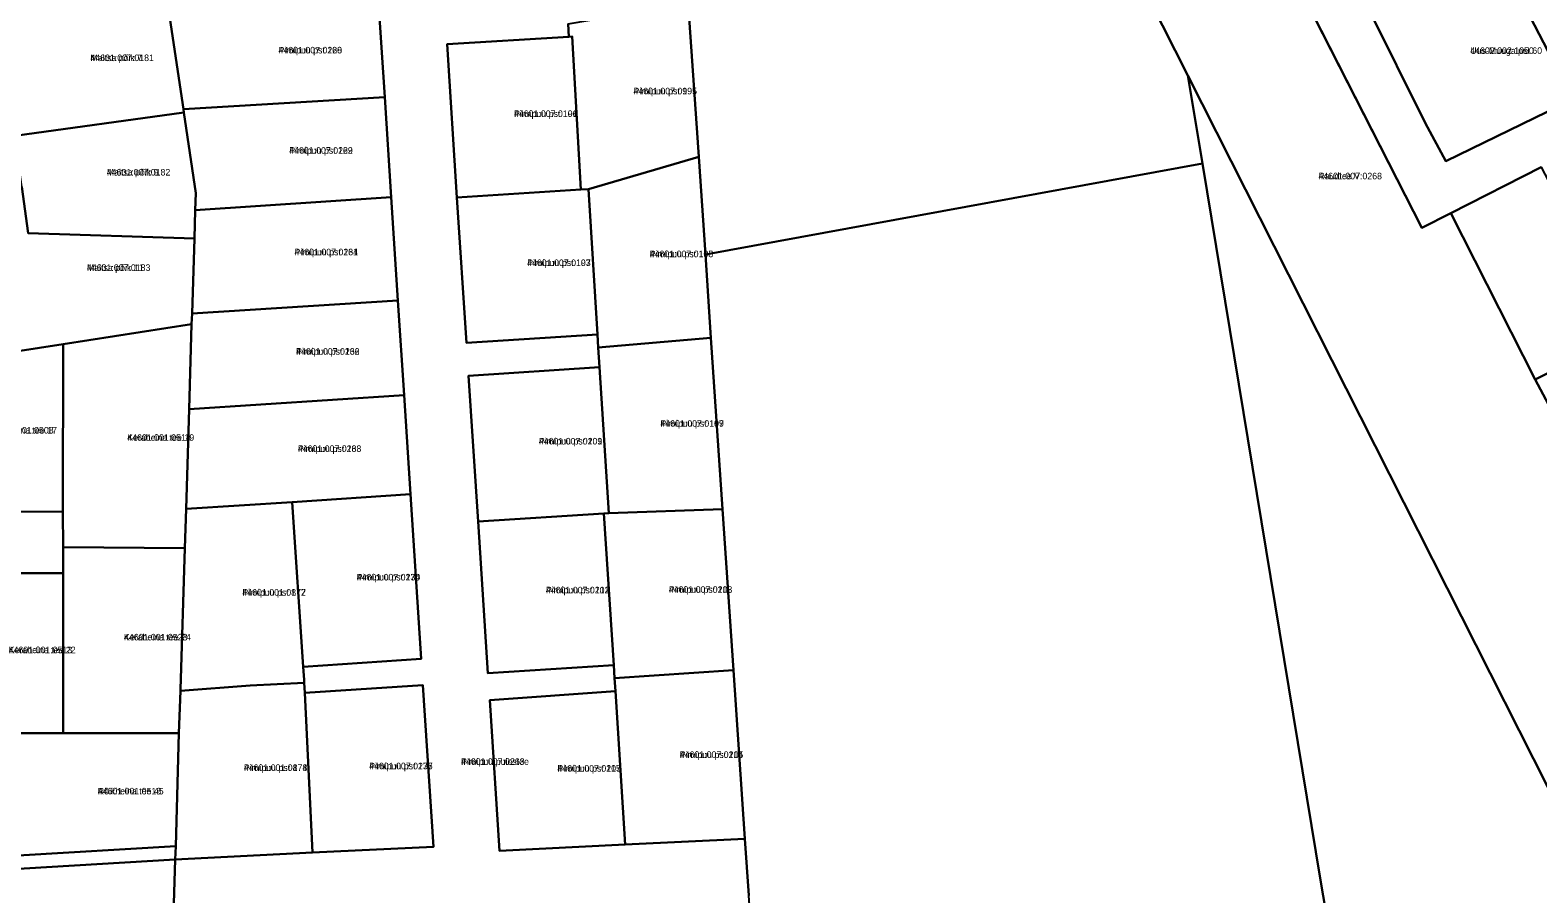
# Model space of a CAD drawing. Extents: x 551843 to 558501, y 6589003 to 6595718.
# Drawn here: x 554378.5 to 554722.9, y 6592716.7 to 6592914.1 of the extents above; entities that cross this region are included whole.
import ezdxf

# ---------------------------------------------------------------- set-up
doc = ezdxf.new("R2010")
doc.units = 0
for name, color, linetype in [('L_AADRESS', 7, 'Continuous'), ('PIIR', 7, 'Continuous'), ('TUNNUS', 7, 'Continuous')]:
    doc.layers.add(name, color=color, linetype=linetype)

msp = doc.modelspace()

# ---------------------------------------------------------------- linework, layer by layer
at = {"layer": 'PIIR'}
for points in [[(554923.69, 6592347.53), (554878.41, 6592438.09), (554841.8, 6592510.41), (554771.18, 6592649.95), (554642.95, 6592903.73), (554573.43, 6593041.09), (554529.22, 6593128.57), (554464.48, 6593256.08), (554446.62, 6593289.09), (554441.09, 6593299.31), (554261.19, 6593527.78)], [(554487.14, 6593279.28), (554574.16, 6593108.63), (554585.26, 6593086.87), (554696.4, 6592868.94), (554702.95, 6592872.25), (554722.28, 6592834.27), (554727.72, 6592823.94)], [(554723.65, 6592882.76), (554702.95, 6592872.25), (554696.4, 6592868.94), (554643.69, 6592972.29), (554655.06, 6592977.69), (554671.09, 6592945.33), (554684.09, 6592919.15), (554697.11, 6592892.89), (554701.82, 6592884.15), (554730.76, 6592898.25)], [(554726.23, 6592907.32), (554712.86, 6592933.09)], [(554411.2, 6592709.5), (554411.66, 6592724.59), (554442.98, 6592726.12), (554470.64, 6592727.48), (554468.24, 6592764.38), (554441.26, 6592762.61), (554441.12, 6592764.9), (554441.11, 6592765.62), (554440.9, 6592768.62), (554467.85, 6592770.38), (554465.4, 6592808.08), (554463.93, 6592830.7), (554462.52, 6592852.34), (554460.98, 6592875.93), (554459.5, 6592898.77), (554458.02, 6592921.54)], [(554501.42, 6592915.58), (554501.57, 6592912.59), (554473.73, 6592910.9), (554476.01, 6592875.84), (554478.17, 6592842.6), (554508.07, 6592844.54), (554508.25, 6592841.54), (554508.55, 6592837.06), (554478.66, 6592835.1), (554480.83, 6592801.77), (554483.08, 6592767.12), (554511.82, 6592768.99), (554512.01, 6592766), (554512.2, 6592763), (554483.48, 6592760.97), (554485.72, 6592726.56), (554514.4, 6592727.96), (554541.78, 6592729.29), (554542.67, 6592716.34)], [(554727.72, 6592823.94), (554722.28, 6592834.27), (554743.42, 6592844.96)]]:
    msp.add_lwpolyline(points, dxfattribs=at)
for points in [[(554521.16, 6593033.4), (554540.12, 6593036.49), (554560.01, 6593039.24), (554573.43, 6593041.09), (554642.95, 6592903.73), (554646.24, 6592883.65), (554532.75, 6592862.8), (554531.22, 6592885.11), (554528.84, 6592920.17), (554526.55, 6592953.9), (554523.81, 6592994.34)], [(554697.11, 6592892.89), (554684.09, 6592919.15), (554712.86, 6592933.09), (554726.23, 6592907.32), (554730.76, 6592898.25), (554701.82, 6592884.15)], [(554371.05, 6592918.84), (554409.37, 6592924.1), (554410.22, 6592918.36), (554413.54, 6592896.01), (554413.66, 6592895.25), (554375.02, 6592889.95)], [(554410.22, 6592918.36), (554458.02, 6592921.54), (554459.5, 6592898.77), (554413.54, 6592896.01)], [(554501.42, 6592915.58), (554528.84, 6592920.17), (554531.22, 6592885.11), (554506.03, 6592877.79), (554504.33, 6592877.68), (554502.32, 6592912.63), (554501.57, 6592912.59)], [(554473.73, 6592910.9), (554501.57, 6592912.59), (554502.32, 6592912.63), (554504.33, 6592877.68), (554476.01, 6592875.84)], [(554745.26, 6592499.11), (554711.7, 6592493.45), (554704.16, 6592538.17), (554673.19, 6592719.82), (554646.24, 6592883.65), (554642.93, 6592903.77), (554771.18, 6592649.95), (554841.8, 6592510.41), (554768.62, 6592501.84)], [(554413.54, 6592896.01), (554459.5, 6592898.77), (554460.98, 6592875.93), (554416.25, 6592872.95), (554416.39, 6592876.86), (554413.66, 6592895.25)], [(554375.02, 6592889.95), (554413.66, 6592895.25), (554416.39, 6592876.86), (554416.25, 6592872.95), (554416.07, 6592866.52), (554378.07, 6592867.69), (554376.62, 6592878.3)], [(554506.03, 6592877.79), (554531.22, 6592885.11), (554532.75, 6592862.8), (554534.02, 6592843.8), (554508.25, 6592841.54), (554508.07, 6592844.54)], [(554534.02, 6592843.8), (554532.75, 6592862.8), (554646.24, 6592883.65), (554673.19, 6592719.82), (554704.16, 6592538.17), (554568.26, 6592508.78), (554555.84, 6592506.03), (554554.24, 6592531.14), (554551.93, 6592568.73), (554549.6, 6592606.49), (554547.29, 6592643.76), (554544.98, 6592681.09), (554544.18, 6592694.26), (554542.67, 6592716.34), (554541.78, 6592729.29), (554539.18, 6592767.79), (554536.68, 6592804.63)], [(554722.28, 6592834.27), (554702.95, 6592872.25), (554723.65, 6592882.76), (554743.42, 6592844.96)], [(554364.77, 6592876.42), (554376.62, 6592878.3), (554378.07, 6592867.69), (554416.07, 6592866.52), (554415.52, 6592849.35), (554415.39, 6592846.94), (554386.06, 6592842.35), (554369.77, 6592839.83)], [(554416.25, 6592872.95), (554460.98, 6592875.93), (554462.52, 6592852.34), (554415.52, 6592849.35), (554416.07, 6592866.52)], [(554476.01, 6592875.84), (554504.33, 6592877.68), (554506.03, 6592877.79), (554508.07, 6592844.54), (554478.17, 6592842.6)], [(554415.52, 6592849.35), (554462.52, 6592852.34), (554463.93, 6592830.7), (554414.85, 6592827.5), (554415.39, 6592846.94)], [(554386.02, 6592804.03), (554386.06, 6592842.35), (554415.39, 6592846.94), (554414.85, 6592827.5), (554414.16, 6592804.69), (554413.87, 6592795.74), (554386.04, 6592795.97)], [(554352.81, 6592804.06), (554352.72, 6592837.18), (554369.77, 6592839.83), (554386.06, 6592842.35), (554386.02, 6592804.03)], [(554508.25, 6592841.54), (554534.02, 6592843.8), (554536.68, 6592804.63), (554510.72, 6592803.72), (554508.55, 6592837.06)], [(554478.66, 6592835.1), (554508.55, 6592837.06), (554510.72, 6592803.72), (554509.57, 6592803.64), (554480.83, 6592801.77)], [(554414.85, 6592827.5), (554463.93, 6592830.7), (554465.4, 6592808.08), (554438.37, 6592806.23), (554414.16, 6592804.69)], [(554269.06, 6592818.81), (554268.83, 6592823.82), (554279.26, 6592825.48), (554282.7, 6592802), (554318.6, 6592802.02), (554352.8, 6592801.98), (554352.81, 6592804.06), (554386.02, 6592804.03), (554386.04, 6592795.97), (554386.03, 6592790), (554361.23, 6592789.98), (554336.17, 6592790.01), (554310.03, 6592790.01), (554281.23, 6592789.98), (554271.27, 6592790.01), (554270.06, 6592806.81)], [(554438.37, 6592806.23), (554465.4, 6592808.08), (554467.85, 6592770.38), (554440.9, 6592768.62)], [(554413.87, 6592795.74), (554414.16, 6592804.69), (554438.37, 6592806.23), (554440.9, 6592768.62), (554441.11, 6592765.62), (554441.12, 6592764.9), (554428.77, 6592764.33), (554412.89, 6592763.14), (554412.86, 6592763.39)], [(554480.83, 6592801.77), (554509.57, 6592803.64), (554511.82, 6592768.99), (554483.08, 6592767.12)], [(554509.57, 6592803.64), (554510.72, 6592803.72), (554536.68, 6592804.63), (554539.18, 6592767.79), (554512.01, 6592766), (554511.82, 6592768.99)], [(554386.03, 6592790), (554386.04, 6592795.97), (554413.87, 6592795.74), (554412.86, 6592763.39), (554412.89, 6592763.14), (554412.52, 6592753.39), (554386.04, 6592753.39)], [(554361.26, 6592753.4), (554361.23, 6592789.98), (554386.03, 6592790), (554386.04, 6592753.39), (554375.81, 6592753.4)], [(554512.01, 6592766), (554539.18, 6592767.79), (554541.78, 6592729.29), (554514.4, 6592727.96), (554512.2, 6592763)], [(554412.52, 6592753.39), (554412.89, 6592763.14), (554428.77, 6592764.33), (554441.12, 6592764.9), (554441.26, 6592762.61), (554442.98, 6592726.12), (554411.66, 6592724.59), (554411.77, 6592727.61)], [(554441.26, 6592762.61), (554468.24, 6592764.38), (554470.64, 6592727.48), (554442.98, 6592726.12)], [(554483.48, 6592760.97), (554512.2, 6592763), (554514.4, 6592727.96), (554485.72, 6592726.56)], [(554375.79, 6592725.47), (554375.81, 6592753.4), (554386.04, 6592753.39), (554412.52, 6592753.39), (554411.77, 6592727.61)], [(554286.44, 6592717.06), (554286.23, 6592720.04), (554313.92, 6592721.75), (554343.7, 6592723.47), (554375.79, 6592725.47), (554411.77, 6592727.61), (554411.66, 6592724.59)], [(554096.53, 6592697.08), (554093.97, 6592709.01), (554118.91, 6592710.02), (554144.94, 6592711.06), (554170.97, 6592712.22), (554197.07, 6592713.42), (554222.84, 6592714.47), (554247.74, 6592715.45), (554276.46, 6592716.41), (554286.44, 6592717.06), (554411.66, 6592724.59), (554411.2, 6592709.5), (554277.28, 6592705.03), (554247.08, 6592703.49), (554216.6, 6592702.26), (554186.13, 6592700.61), (554137.12, 6592698.41)]]:
    msp.add_lwpolyline(points, close=True, dxfattribs=at)

# ---------------------------------------------------------------- texts
at = {"layer": 'L_AADRESS'}
for s, p in [('Pirnipuu pst 160', (554435.25, 6592908.78)), ('Uus-Muuga pst 60', (554707.43, 6592908.67)), ('Maltsa põik 7', (554392.29, 6592907.03)), ('Pirnipuu pst 99', (554516.32, 6592899.43)), ('Pirnipuu pst 101', (554489.03, 6592894.26)), ('Pirnipuu pst 162', (554437.7, 6592885.86)), ('Maltsa põik 9', (554396.03, 6592880.88)), ('Raudtee V', (554672.76, 6592880.01)), ('Pirnipuu pst 164', (554438.9, 6592862.64)), ('Pirnipuu pst 103', (554492.04, 6592860.19)), ('Pirnipuu pst 105', (554520.03, 6592862.21)), ('Maltsa põik 11', (554391.49, 6592859.07)), ('Pirnipuu pst 166', (554439.26, 6592839.92)), ('Pirnipuu pst 107', (554522.46, 6592823.46)), ('Keraheina tee 17', (554369.39, 6592821.91)), ('Keraheina tee 19', (554400.71, 6592820.25)), ('Pirnipuu pst 109', (554494.69, 6592819.41)), ('Pirnipuu pst 168', (554439.66, 6592817.7)), ('Pirnipuu pst 170', (554453.11, 6592788.33)), ('Pirnipuu pst 172', (554426.99, 6592784.85)), ('Pirnipuu pst 111', (554496.32, 6592785.38)), ('Pirnipuu pst 113', (554524.38, 6592785.51)), ('Keraheina tee 24', (554399.95, 6592774.62)), ('Keraheina tee 22', (554373.63, 6592771.7)), ('Pirnipuu pst 115', (554526.89, 6592747.77)), ('Pirnipuu pst 174', (554427.32, 6592744.79)), ('Pirnipuu pst 176', (554455.95, 6592745.17)), ('Pirnipuu puiestee', (554476.94, 6592746.19)), ('Pirnipuu pst 117', (554498.94, 6592744.63)), ('Rõikheina tee 45', (554393.96, 6592739.43))]:
    msp.add_text(s, height=1.5, dxfattribs=at).set_placement(p)
at = {"layer": 'TUNNUS'}
for s, p in [('44601:007:0228', (554435.25, 6592908.78)), ('44602:002:1050', (554707.43, 6592908.67)), ('44601:007:0181', (554392.29, 6592907.03)), ('44601:007:0195', (554516.32, 6592899.43)), ('44601:007:0196', (554489.03, 6592894.26)), ('44601:007:0229', (554437.7, 6592885.86)), ('44601:007:0182', (554396.03, 6592880.88)), ('44601:007:0268', (554672.76, 6592880.01)), ('44601:007:0231', (554438.9, 6592862.64)), ('44601:007:0197', (554492.04, 6592860.19)), ('44601:007:0198', (554520.03, 6592862.21)), ('44601:007:0183', (554391.49, 6592859.07)), ('44601:007:0232', (554439.26, 6592839.92)), ('44601:007:0199', (554522.46, 6592823.46)), ('44601:001:0508', (554369.39, 6592821.91)), ('44601:001:0514', (554400.71, 6592820.25)), ('44601:007:0201', (554494.69, 6592819.41)), ('44601:007:0233', (554439.66, 6592817.7)), ('44601:007:0234', (554453.11, 6592788.33)), ('44601:001:0877', (554426.99, 6592784.85)), ('44601:007:0202', (554496.32, 6592785.38)), ('44601:007:0203', (554524.38, 6592785.51)), ('44601:001:0523', (554399.95, 6592774.62)), ('44601:001:0513', (554373.63, 6592771.7)), ('44601:007:0204', (554526.89, 6592747.77)), ('44601:001:0878', (554427.32, 6592744.79)), ('44601:007:0237', (554455.95, 6592745.17)), ('44601:007:0263', (554476.94, 6592746.19)), ('44601:007:0205', (554498.94, 6592744.63)), ('44601:001:0518', (554393.96, 6592739.43))]:
    msp.add_text(s, height=1.5, dxfattribs=at).set_placement(p)

doc.saveas('drawing.dxf')
